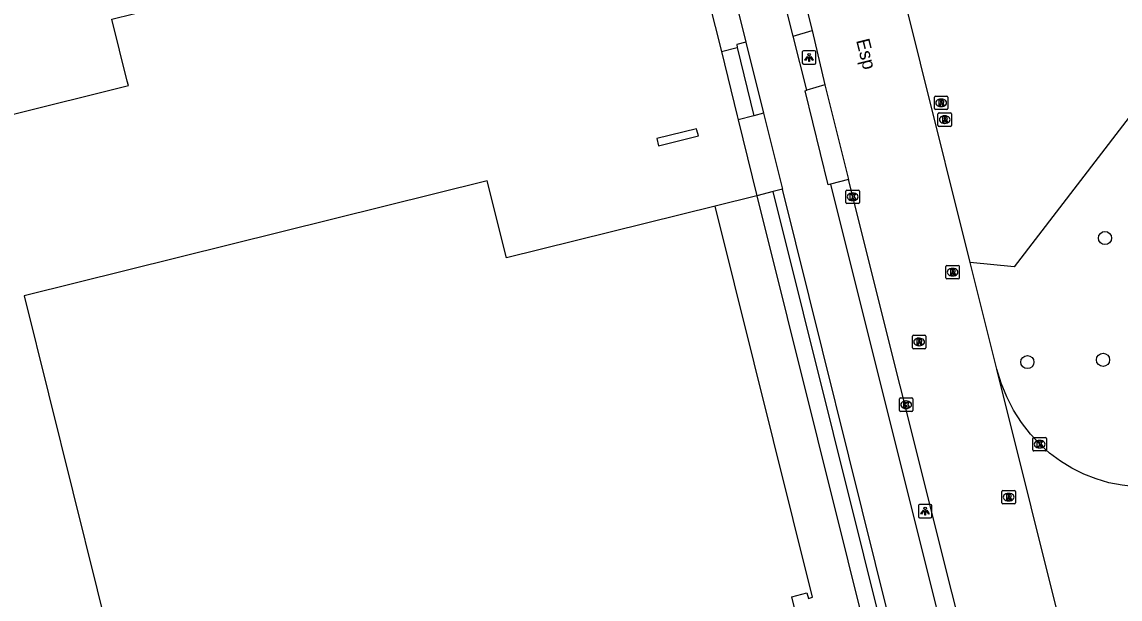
# Model space of a CAD drawing. Extents: x 161389 to 162585, y 388479 to 389761.
# Drawn here: x 162131.8 to 162213.4, y 388865.1 to 388908 of the extents above; entities that cross this region are included whole.
import ezdxf

# ---------------------------------------------------------------- set-up
doc = ezdxf.new("R2010")
doc.units = 0
for name, color, linetype in [('IMGEO_Boom', 7, 'Continuous'), ('IMGEO_Fietspad_gesloten', 7, 'Continuous'), ('IMGEO_Groenvoorziening', 7, 'Continuous'), ('IMGEO_Kolk', 7, 'Continuous'), ('IMGEO_Lichtpunt', 7, 'Continuous'), ('IMGEO_Openbare_ruimte_label', 7, 'Continuous'), ('IMGEO_Pand', 7, 'Continuous'), ('IMGEO_Rijbaan_lokaal_gesloten', 7, 'Continuous'), ('IMGEO_Rioolput', 7, 'Continuous'), ('IMGEO_Voetpad_open', 7, 'Continuous')]:
    doc.layers.add(name, color=color, linetype=linetype)

msp = doc.modelspace()

# ---------------------------------------------------------------- linework, layer by layer
at = {"layer": 'IMGEO_Boom'}
for centre in [(162212.324, 388891.939), (162206.556, 388882.724), (162212.177, 388882.893)]:
    msp.add_circle(centre, 0.489, dxfattribs=at)
at = {"layer": 'IMGEO_Fietspad_gesloten'}
for points in [[(162189.162, 388906.938), (162185.895, 388919.999)], [(162182.503, 388919.118), (162185.642, 388906.491)], [(162190.167, 388902.919), (162189.162, 388906.938)], [(162185.642, 388906.491), (162186.955, 388901.209)], [(162191.915, 388895.933), (162191.743, 388895.888), (162190.041, 388902.881), (162190.167, 388902.919)], [(162186.955, 388901.209), (162188.36, 388895.556)], [(162191.915, 388895.933), (162207.606, 388833.207)], [(162204.161, 388831.979), (162188.36, 388895.556)]]:
    msp.add_lwpolyline(points, dxfattribs=at)
at = {"layer": 'IMGEO_Groenvoorziening'}
for points in [[(162240.417, 388950.904), (162226.358, 388916.854), (162205.565, 388889.805), (162202.309, 388890.111)], [(162186.448, 388895.081), (162183.364, 388894.315)]]:
    msp.add_lwpolyline(points, dxfattribs=at)
at = {"layer": 'IMGEO_Kolk'}
for p, q in [((162193.075, 388894.575), (162193.075, 388895.427)), ((162193.15, 388895.501), (162194.002, 388895.501)), ((162193.563, 388895.281), (162193.588, 388895.281)), ((162194.076, 388895.427), (162194.076, 388894.575)), ((162194.002, 388894.501), (162193.15, 388894.501)), ((162193.586, 388894.721), (162193.561, 388894.721)), ((162197.046, 388879.131), (162197.046, 388879.983)), ((162197.121, 388880.057), (162197.973, 388880.057)), ((162197.534, 388879.837), (162197.559, 388879.837)), ((162198.047, 388879.983), (162198.047, 388879.131)), ((162197.973, 388879.057), (162197.121, 388879.057)), ((162197.557, 388879.277), (162197.532, 388879.277)), ((162206.971, 388876.196), (162206.971, 388877.048)), ((162207.046, 388877.122), (162207.898, 388877.122)), ((162207.482, 388876.342), (162207.457, 388876.342)), ((162207.459, 388876.902), (162207.484, 388876.902)), ((162207.972, 388877.048), (162207.972, 388876.196)), ((162207.898, 388876.122), (162207.046, 388876.122))]:
    msp.add_line(p, q, dxfattribs=at)
for points in [[(162193.075, 388894.575), (162193.075, 388895.427)], [(162193.15, 388895.501), (162194.002, 388895.501)], [(162193.396, 388895.201), (162193.519, 388895.201), (162193.519, 388895.05), (162193.649, 388895.201), (162193.813, 388895.201), (162193.667, 388895.05), (162193.82, 388894.801), (162193.668, 388894.801), (162193.583, 388894.965), (162193.519, 388894.898), (162193.519, 388894.801), (162193.396, 388894.801), (162193.396, 388895.201)], [(162194.076, 388895.427), (162194.076, 388894.575)], [(162194.002, 388894.501), (162193.15, 388894.501)], [(162197.046, 388879.131), (162197.046, 388879.983)], [(162197.121, 388880.057), (162197.973, 388880.057)], [(162197.367, 388879.757), (162197.49, 388879.757), (162197.49, 388879.606), (162197.62, 388879.757), (162197.784, 388879.757), (162197.638, 388879.606), (162197.791, 388879.357), (162197.639, 388879.357), (162197.554, 388879.521), (162197.49, 388879.454), (162197.49, 388879.357), (162197.367, 388879.357), (162197.367, 388879.757)], [(162198.047, 388879.983), (162198.047, 388879.131)], [(162197.973, 388879.057), (162197.121, 388879.057)], [(162206.971, 388876.196), (162206.971, 388877.048)], [(162207.046, 388877.122), (162207.898, 388877.122)], [(162207.292, 388876.822), (162207.415, 388876.822), (162207.415, 388876.671), (162207.545, 388876.822), (162207.709, 388876.822), (162207.563, 388876.671), (162207.716, 388876.422), (162207.564, 388876.422), (162207.479, 388876.586), (162207.415, 388876.519), (162207.415, 388876.422), (162207.292, 388876.422), (162207.292, 388876.822)], [(162207.972, 388877.048), (162207.972, 388876.196)], [(162207.898, 388876.122), (162207.046, 388876.122)]]:
    msp.add_lwpolyline(points, dxfattribs=at)
for centre, start, end in [((162193.152, 388895.425), 91.55205, 178.44795), ((162193.152, 388895.425), 91.55205, 178.44795), ((162194, 388895.425), 1.55205, 88.44795), ((162194, 388895.425), 1.55205, 88.44795), ((162193.152, 388894.577), 181.55205, 268.44795), ((162193.152, 388894.577), 181.55205, 268.44795), ((162194, 388894.577), 271.55205, 358.44795), ((162194, 388894.577), 271.55205, 358.44795), ((162197.123, 388879.981), 91.55205, 178.44795), ((162197.123, 388879.981), 91.55205, 178.44795), ((162197.971, 388879.981), 1.55205, 88.44795), ((162197.971, 388879.981), 1.55205, 88.44795), ((162197.123, 388879.133), 181.55205, 268.44795), ((162197.123, 388879.133), 181.55205, 268.44795), ((162197.971, 388879.133), 271.55205, 358.44795), ((162197.971, 388879.133), 271.55205, 358.44795), ((162207.048, 388877.046), 91.55205, 178.44795), ((162207.048, 388877.046), 91.55205, 178.44795), ((162207.896, 388877.046), 1.55205, 88.44795), ((162207.896, 388877.046), 1.55205, 88.44795), ((162207.048, 388876.198), 181.55205, 268.44795), ((162207.048, 388876.198), 181.55205, 268.44795), ((162207.896, 388876.198), 271.55205, 358.44795), ((162207.896, 388876.198), 271.55205, 358.44795)]:
    msp.add_arc(centre, 0.0765, start, end, dxfattribs=at)
for centre, major_axis, ratio, start_param, end_param in [((162193.562, 388895.001), (-0.387, 0.002), 0.722429, 4.712389, 7.853982), ((162193.587, 388895.001), (-0.39, 0.002), 0.717154, 1.570796, 4.712389), ((162197.533, 388879.557), (-0.387, 0.002), 0.722429, 4.712389, 7.853982), ((162197.558, 388879.557), (-0.39, 0.002), 0.717154, 1.570796, 4.712389), ((162207.458, 388876.622), (-0.387, 0.002), 0.722429, 4.712389, 7.853982), ((162207.483, 388876.622), (-0.39, 0.002), 0.717154, 1.570796, 4.712389)]:
    msp.add_ellipse(centre, major_axis=major_axis, ratio=ratio, start_param=start_param, end_param=end_param, dxfattribs=at)
at = {"layer": 'IMGEO_Lichtpunt'}
for p, q in [((162189.833, 388905.76), (162189.833, 388904.953)), ((162189.833, 388905.76), (162189.833, 388904.953)), ((162190.735, 388905.855), (162189.927, 388905.855)), ((162190.735, 388905.855), (162189.927, 388905.855)), ((162190.829, 388904.953), (162190.829, 388905.76)), ((162190.829, 388904.953), (162190.829, 388905.76)), ((162189.927, 388904.859), (162190.735, 388904.859)), ((162189.927, 388904.859), (162190.735, 388904.859)), ((162198.458, 388872.061), (162198.458, 388871.254)), ((162198.458, 388872.061), (162198.458, 388871.254)), ((162199.36, 388872.156), (162198.552, 388872.156)), ((162199.36, 388872.156), (162198.552, 388872.156)), ((162199.454, 388871.254), (162199.454, 388872.061)), ((162199.454, 388871.254), (162199.454, 388872.061)), ((162198.552, 388871.16), (162199.36, 388871.16)), ((162198.552, 388871.16), (162199.36, 388871.16))]:
    msp.add_line(p, q, dxfattribs=at)
for points in [[(162190.207, 388905.424), (162190.246, 388905.396), (162190.058, 388905.134), (162190.02, 388905.161), (162190.207, 388905.424)], [(162190.309, 388905.376), (162190.356, 388905.376), (162190.356, 388905.054), (162190.309, 388905.054), (162190.309, 388905.376)], [(162190.419, 388905.396), (162190.457, 388905.423), (162190.644, 388905.161), (162190.605, 388905.133), (162190.419, 388905.396)], [(162198.832, 388871.725), (162198.871, 388871.697), (162198.683, 388871.435), (162198.645, 388871.462), (162198.832, 388871.725)], [(162198.934, 388871.677), (162198.981, 388871.677), (162198.981, 388871.355), (162198.934, 388871.355), (162198.934, 388871.677)], [(162199.044, 388871.697), (162199.082, 388871.724), (162199.269, 388871.462), (162199.23, 388871.434), (162199.044, 388871.697)]]:
    msp.add_lwpolyline(points, dxfattribs=at)
for centre in [(162190.332, 388905.558), (162198.957, 388871.859)]:
    msp.add_circle(centre, 0.0994, dxfattribs=at)
for centre, start, end in [((162189.927, 388905.76), 90, 180), ((162189.927, 388905.76), 90, 180), ((162190.735, 388905.76), 0, 90), ((162190.735, 388905.76), 0, 90), ((162189.927, 388904.953), 180, 270), ((162189.927, 388904.953), 180, 270), ((162190.735, 388904.953), 270, 0), ((162190.735, 388904.953), 270, 360), ((162198.552, 388872.061), 90, 180), ((162198.552, 388872.061), 90, 180), ((162199.36, 388872.061), 0, 90), ((162199.36, 388872.061), 0, 90), ((162198.552, 388871.254), 180, 270), ((162198.552, 388871.254), 180, 270), ((162199.36, 388871.254), 270, 0), ((162199.36, 388871.254), 270, 360)]:
    msp.add_arc(centre, 0.0946, start, end, dxfattribs=at)
at = {"layer": 'IMGEO_Pand'}
for points in [[(162097.709, 388959.487), (162111.134, 388905.465), (162113.318, 388896.678), (162139.769, 388903.263), (162139.672, 388903.596), (162138.538, 388908.194), (162177.16, 388917.737), (162177.572, 388917.843)], [(162181.979, 388900.056), (162179.029, 388899.32), (162179.159, 388898.799), (162182.109, 388899.534), (162182.005, 388899.95), (162181.979, 388900.056)], [(162183.364, 388894.315), (162167.852, 388890.466), (162166.416, 388896.18), (162132.018, 388887.649), (162146.475, 388829.422)], [(162197.59, 388830.934), (162189.064, 388865.285), (162190.162, 388865.576), (162190.288, 388865.174), (162190.591, 388865.254), (162183.364, 388894.315)]]:
    msp.add_lwpolyline(points, dxfattribs=at)
at = {"layer": 'IMGEO_Rijbaan_lokaal_gesloten'}
for points in [[(162202.309, 388890.111), (162191.224, 388934.569), (162186.365, 388954.055)], [(162187.309, 388920.388), (162187.85, 388918.21), (162190.561, 388907.35)], [(162190.561, 388907.35), (162191.505, 388903.316)], [(162191.505, 388903.316), (162193.265, 388896.286)], [(162211.426, 388823.482), (162207.148, 388840.97), (162202.335, 388860.2), (162200.937, 388865.633), (162193.265, 388896.286)], [(162204.281, 388882.203), (162202.309, 388890.111)], [(162211.929, 388851.522), (162204.281, 388882.203)], [(162237.058, 388871.444), (162235.953, 388871.543), (162215.116, 388873.448), (162214.581, 388873.467), (162213.594, 388873.571), (162212.619, 388873.762), (162211.666, 388874.04), (162210.741, 388874.402), (162209.852, 388874.845), (162209.006, 388875.365), (162208.211, 388875.959), (162207.471, 388876.622), (162206.784, 388877.37), (162206.114, 388878.239), (162205.524, 388879.164), (162205.02, 388880.139), (162204.604, 388881.154), (162204.281, 388882.203)]]:
    msp.add_lwpolyline(points, dxfattribs=at)
at = {"layer": 'IMGEO_Rioolput'}
for p, q in [((162199.724, 388902.48), (162200.576, 388902.48)), ((162199.649, 388901.554), (162199.649, 388902.406)), ((162200.16, 388901.7), (162200.135, 388901.7)), ((162200.137, 388902.26), (162200.162, 388902.26)), ((162200.65, 388902.406), (162200.65, 388901.554)), ((162200.576, 388901.48), (162199.724, 388901.48)), ((162199.915, 388900.308), (162199.915, 388901.16)), ((162199.99, 388901.234), (162200.842, 388901.234)), ((162200.403, 388901.014), (162200.428, 388901.014)), ((162200.916, 388901.16), (162200.916, 388900.308)), ((162200.842, 388900.234), (162199.99, 388900.234)), ((162200.426, 388900.454), (162200.401, 388900.454)), ((162200.499, 388888.98), (162200.499, 388889.832)), ((162200.574, 388889.906), (162201.426, 388889.906)), ((162200.987, 388889.686), (162201.012, 388889.686)), ((162201.5, 388889.832), (162201.5, 388888.98)), ((162201.426, 388888.906), (162200.574, 388888.906)), ((162201.01, 388889.126), (162200.985, 388889.126)), ((162198.015, 388883.792), (162198.015, 388884.644)), ((162198.09, 388884.718), (162198.942, 388884.718)), ((162198.503, 388884.498), (162198.528, 388884.498)), ((162199.016, 388884.644), (162199.016, 388883.792)), ((162198.942, 388883.718), (162198.09, 388883.718)), ((162198.526, 388883.938), (162198.501, 388883.938)), ((162204.663, 388872.267), (162204.663, 388873.119)), ((162204.738, 388873.193), (162205.59, 388873.193)), ((162205.664, 388873.119), (162205.664, 388872.267)), ((162205.174, 388872.413), (162205.149, 388872.413)), ((162205.151, 388872.973), (162205.176, 388872.973)), ((162205.59, 388872.193), (162204.738, 388872.193))]:
    msp.add_line(p, q, dxfattribs=at)
for points in [[(162199.724, 388902.48), (162200.576, 388902.48)], [(162199.649, 388901.554), (162199.649, 388902.406)], [(162200.238, 388902.178), (162199.986, 388902.18), (162199.986, 388901.78)], [(162199.986, 388901.78), (162200.11, 388901.78), (162200.11, 388901.942), (162200.121, 388901.942)], [(162200.164, 388902.099), (162200.11, 388902.099), (162200.11, 388902.018)], [(162200.11, 388902.018), (162200.162, 388902.018)], [(162200.168, 388901.913), (162200.239, 388901.78), (162200.379, 388901.78), (162200.314, 388901.906)], [(162200.65, 388902.406), (162200.65, 388901.554)], [(162200.576, 388901.48), (162199.724, 388901.48)], [(162199.915, 388900.308), (162199.915, 388901.16)], [(162199.99, 388901.234), (162200.842, 388901.234)], [(162200.504, 388900.932), (162200.252, 388900.934), (162200.252, 388900.534)], [(162200.43, 388900.853), (162200.376, 388900.853), (162200.376, 388900.772)], [(162200.916, 388901.16), (162200.916, 388900.308)], [(162200.842, 388900.234), (162199.99, 388900.234)], [(162200.252, 388900.534), (162200.376, 388900.534), (162200.376, 388900.696), (162200.387, 388900.696)], [(162200.376, 388900.772), (162200.428, 388900.772)], [(162200.434, 388900.667), (162200.505, 388900.534), (162200.645, 388900.534), (162200.58, 388900.66)], [(162200.499, 388888.98), (162200.499, 388889.832)], [(162200.574, 388889.906), (162201.426, 388889.906)], [(162201.088, 388889.604), (162200.836, 388889.606), (162200.836, 388889.206)], [(162201.014, 388889.525), (162200.96, 388889.525), (162200.96, 388889.444)], [(162200.96, 388889.444), (162201.012, 388889.444)], [(162201.5, 388889.832), (162201.5, 388888.98)], [(162201.426, 388888.906), (162200.574, 388888.906)], [(162200.836, 388889.206), (162200.96, 388889.206), (162200.96, 388889.368), (162200.971, 388889.368)], [(162201.018, 388889.339), (162201.089, 388889.206), (162201.229, 388889.206), (162201.164, 388889.332)], [(162198.015, 388883.792), (162198.015, 388884.644)], [(162198.09, 388884.718), (162198.942, 388884.718)], [(162199.016, 388884.644), (162199.016, 388883.792)], [(162198.942, 388883.718), (162198.09, 388883.718)], [(162198.604, 388884.416), (162198.352, 388884.418), (162198.352, 388884.018)], [(162198.352, 388884.018), (162198.476, 388884.018), (162198.476, 388884.18), (162198.487, 388884.18)], [(162198.53, 388884.337), (162198.476, 388884.337), (162198.476, 388884.256)], [(162198.476, 388884.256), (162198.528, 388884.256)], [(162198.534, 388884.151), (162198.605, 388884.018), (162198.745, 388884.018), (162198.68, 388884.144)], [(162204.663, 388872.267), (162204.663, 388873.119)], [(162204.738, 388873.193), (162205.59, 388873.193)], [(162205.664, 388873.119), (162205.664, 388872.267)], [(162205.252, 388872.891), (162205, 388872.893), (162205, 388872.493)], [(162205, 388872.493), (162205.124, 388872.493), (162205.124, 388872.655), (162205.135, 388872.655)], [(162205.178, 388872.812), (162205.124, 388872.812), (162205.124, 388872.731)], [(162205.124, 388872.731), (162205.176, 388872.731)], [(162205.182, 388872.626), (162205.253, 388872.493), (162205.393, 388872.493), (162205.328, 388872.619)], [(162205.59, 388872.193), (162204.738, 388872.193)]]:
    msp.add_lwpolyline(points, dxfattribs=at)
for centre, radius, start, end in [((162199.726, 388902.404), 0.0765, 91.55205, 178.44795), ((162199.726, 388902.404), 0.0765, 91.55205, 178.44795), ((162200.574, 388902.404), 0.0765, 1.55205, 88.44795), ((162200.574, 388902.404), 0.0765, 1.55205, 88.44795), ((162200.12, 388901.889), 0.0533, 26.02933, 88.69889), ((162200.146, 388902.207), 0.19, 274.7715, 282.96867), ((162200.17, 388902.003), 0.0964, 77.00612, 93.18647), ((162200.184, 388902.06), 0.0378, 276.66336, 79.67722), ((162200.237, 388902.068), 0.109, 350.36119, 89.41601), ((162200.235, 388902.068), 0.112, 277.58423, 350.98172), ((162200.219, 388901.853), 0.108, 29.51342, 73.79051), ((162199.726, 388901.556), 0.0765, 181.55205, 268.44795), ((162199.726, 388901.556), 0.0765, 181.55205, 268.44795), ((162199.992, 388901.158), 0.0765, 91.55205, 178.44795), ((162199.992, 388901.158), 0.0765, 91.55205, 178.44795), ((162200.436, 388900.757), 0.0964, 77.00612, 93.18647), ((162200.45, 388900.814), 0.0378, 276.66336, 79.67722), ((162200.503, 388900.822), 0.109, 350.36119, 89.41601), ((162200.574, 388901.556), 0.0765, 271.55205, 358.44795), ((162200.574, 388901.556), 0.0765, 271.55205, 358.44795), ((162200.84, 388901.158), 0.0765, 1.55205, 88.44795), ((162200.84, 388901.158), 0.0765, 1.55205, 88.44795), ((162199.992, 388900.31), 0.0765, 181.55205, 268.44795), ((162199.992, 388900.31), 0.0765, 181.55205, 268.44795), ((162200.386, 388900.643), 0.0533, 26.02933, 88.69889), ((162200.412, 388900.961), 0.19, 274.7715, 282.96867), ((162200.501, 388900.822), 0.112, 277.58423, 350.98172), ((162200.485, 388900.607), 0.108, 29.51342, 73.79051), ((162200.84, 388900.31), 0.0765, 271.55205, 358.44795), ((162200.84, 388900.31), 0.0765, 271.55205, 358.44795), ((162200.576, 388889.83), 0.0765, 91.55205, 178.44795), ((162200.576, 388889.83), 0.0765, 91.55205, 178.44795), ((162200.996, 388889.633), 0.19, 274.7715, 282.96867), ((162201.02, 388889.429), 0.0964, 77.00612, 93.18647), ((162201.034, 388889.486), 0.0378, 276.66336, 79.67722), ((162201.087, 388889.494), 0.109, 350.36119, 89.41601), ((162201.085, 388889.494), 0.112, 277.58423, 350.98172), ((162201.424, 388889.83), 0.0765, 1.55205, 88.44795), ((162201.424, 388889.83), 0.0765, 1.55205, 88.44795), ((162200.576, 388888.982), 0.0765, 181.55205, 268.44795), ((162200.576, 388888.982), 0.0765, 181.55205, 268.44795), ((162200.97, 388889.315), 0.0533, 26.02933, 88.69889), ((162201.069, 388889.279), 0.108, 29.51342, 73.79051), ((162201.424, 388888.982), 0.0765, 271.55205, 358.44795), ((162201.424, 388888.982), 0.0765, 271.55205, 358.44795), ((162198.092, 388884.642), 0.0765, 91.55205, 178.44795), ((162198.092, 388884.642), 0.0765, 91.55205, 178.44795), ((162198.94, 388884.642), 0.0765, 1.55205, 88.44795), ((162198.94, 388884.642), 0.0765, 1.55205, 88.44795), ((162198.092, 388883.794), 0.0765, 181.55205, 268.44795), ((162198.092, 388883.794), 0.0765, 181.55205, 268.44795), ((162198.486, 388884.127), 0.0533, 26.02933, 88.69889), ((162198.512, 388884.445), 0.19, 274.7715, 282.96867), ((162198.536, 388884.241), 0.0964, 77.00612, 93.18647), ((162198.55, 388884.298), 0.0378, 276.66336, 79.67722), ((162198.603, 388884.306), 0.109, 350.36119, 89.41601), ((162198.601, 388884.306), 0.112, 277.58423, 350.98172), ((162198.585, 388884.091), 0.108, 29.51342, 73.79051), ((162198.94, 388883.794), 0.0765, 271.55205, 358.44795), ((162198.94, 388883.794), 0.0765, 271.55205, 358.44795), ((162204.74, 388873.117), 0.0765, 91.55205, 178.44795), ((162204.74, 388873.117), 0.0765, 91.55205, 178.44795), ((162205.588, 388873.117), 0.0765, 1.55205, 88.44795), ((162205.588, 388873.117), 0.0765, 1.55205, 88.44795), ((162204.74, 388872.269), 0.0765, 181.55205, 268.44795), ((162204.74, 388872.269), 0.0765, 181.55205, 268.44795), ((162205.134, 388872.602), 0.0533, 26.02933, 88.69889), ((162205.16, 388872.92), 0.19, 274.7715, 282.96867), ((162205.184, 388872.716), 0.0964, 77.00612, 93.18647), ((162205.198, 388872.773), 0.0378, 276.66336, 79.67722), ((162205.251, 388872.781), 0.109, 350.36119, 89.41601), ((162205.249, 388872.781), 0.112, 277.58423, 350.98172), ((162205.233, 388872.566), 0.108, 29.51342, 73.79051), ((162205.588, 388872.269), 0.0765, 271.55205, 358.44795), ((162205.588, 388872.269), 0.0765, 271.55205, 358.44795)]:
    msp.add_arc(centre, radius, start, end, dxfattribs=at)
for centre, major_axis, ratio, start_param, end_param in [((162200.136, 388901.98), (-0.387, 0.002), 0.722429, 4.712389, 7.853982), ((162200.161, 388901.98), (-0.39, 0.002), 0.717154, 1.570796, 4.712389), ((162200.402, 388900.734), (-0.387, 0.002), 0.722429, 4.712389, 7.853982), ((162200.427, 388900.734), (-0.39, 0.002), 0.717154, 1.570796, 4.712389), ((162200.986, 388889.406), (-0.387, 0.002), 0.722429, 4.712389, 7.853982), ((162201.011, 388889.406), (-0.39, 0.002), 0.717154, 1.570796, 4.712389), ((162198.502, 388884.218), (-0.387, 0.002), 0.722429, 4.712389, 7.853982), ((162198.527, 388884.218), (-0.39, 0.002), 0.717154, 1.570796, 4.712389), ((162205.15, 388872.693), (-0.387, 0.002), 0.722429, 4.712389, 7.853982), ((162205.175, 388872.693), (-0.39, 0.002), 0.717154, 1.570796, 4.712389)]:
    msp.add_ellipse(centre, major_axis=major_axis, ratio=ratio, start_param=start_param, end_param=end_param, dxfattribs=at)
at = {"layer": 'IMGEO_Voetpad_open'}
for points in [[(162180.574, 388918.618), (162183.819, 388905.803)], [(162189.162, 388906.938), (162190.561, 388907.35)], [(162183.819, 388905.803), (162184.996, 388906.096)], [(162183.819, 388905.803), (162184.992, 388901.004), (162185.059, 388900.727)], [(162185.642, 388906.491), (162184.956, 388906.316), (162184.996, 388906.096)], [(162184.996, 388906.096), (162186.241, 388901.026)], [(162191.505, 388903.316), (162190.167, 388902.919)], [(162186.241, 388901.026), (162185.059, 388900.727)], [(162186.955, 388901.209), (162186.241, 388901.026)], [(162185.059, 388900.727), (162186.448, 388895.081)], [(162193.265, 388896.286), (162191.915, 388895.933)], [(162187.678, 388895.387), (162186.448, 388895.081)], [(162188.36, 388895.556), (162187.678, 388895.387)], [(162197.816, 388810.478), (162198.971, 388810.158), (162199.262, 388811.491), (162203.372, 388829.992), (162203.503, 388831.163), (162203.383, 388832.334), (162187.678, 388895.387)], [(162186.448, 388895.081), (162202.214, 388831.899), (162202.283, 388830.935), (162202.145, 388829.978), (162200.919, 388824.477)]]:
    msp.add_lwpolyline(points, dxfattribs=at)

# ---------------------------------------------------------------- texts
at = {"layer": 'IMGEO_Openbare_ruimte_label'}
msp.add_text('Esp', height=1, rotation=284.00844, dxfattribs=at).set_placement((162193.824, 388906.612))

doc.saveas('drawing.dxf')
